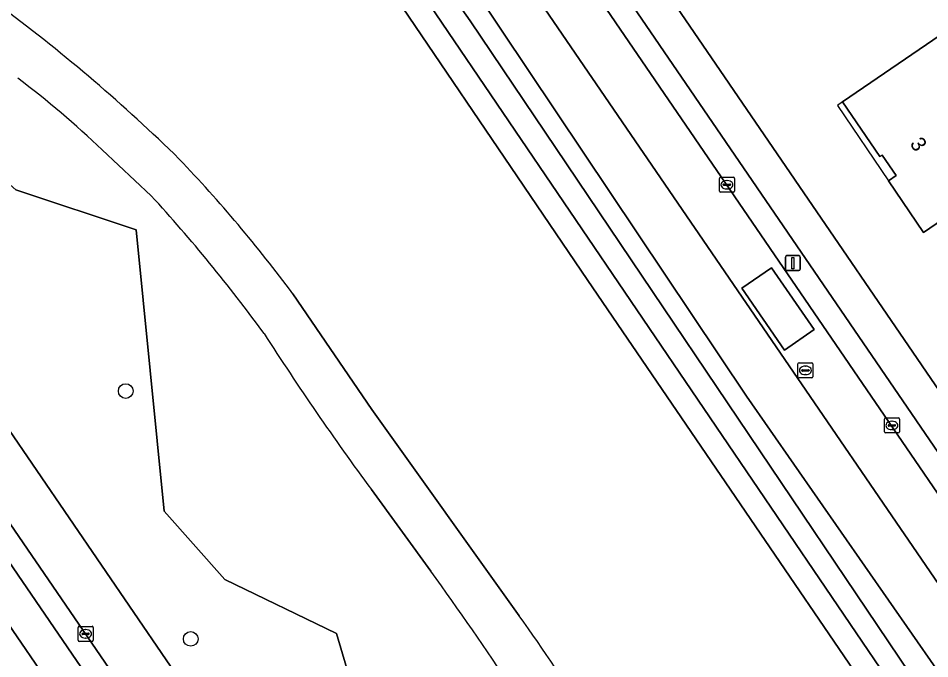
# Model space of a CAD drawing. Extents: x 155275 to 156265, y 382654 to 383635.
# Drawn here: x 155646.9 to 155707.5, y 383225.8 to 383268.4 of the extents above; entities that cross this region are included whole.
import ezdxf

# ---------------------------------------------------------------- set-up
doc = ezdxf.new("R2010")
doc.units = 0
for name, color, linetype in [('IMGEO_Boom', 7, 'Continuous'), ('IMGEO_Erf', 7, 'Continuous'), ('IMGEO_Fietspad_gesloten', 7, 'Continuous'), ('IMGEO_Gemengd_bos', 7, 'Continuous'), ('IMGEO_Groenvoorziening', 7, 'Continuous'), ('IMGEO_Haag', 7, 'Continuous'), ('IMGEO_Kolk', 7, 'Continuous'), ('IMGEO_Lichtmast', 7, 'Continuous'), ('IMGEO_Loofbos', 7, 'Continuous'), ('IMGEO_Oever', 7, 'Continuous'), ('IMGEO_Pand', 7, 'Continuous'), ('IMGEO_Pand_nummerreeks', 7, 'Continuous'), ('IMGEO_Pand_overbouw', 7, 'Continuous'), ('IMGEO_Rijbaan_lokaal_gesloten', 7, 'Continuous'), ('IMGEO_Rijbaan_lokaal_open', 7, 'Continuous'), ('IMGEO_Rioolput', 7, 'Continuous'), ('IMGEO_Voetpad_open', 7, 'Continuous'), ('IMGEO_Waterloop', 7, 'Continuous')]:
    doc.layers.add(name, color=color, linetype=linetype)

msp = doc.modelspace()

# ---------------------------------------------------------------- linework, layer by layer
at = {"layer": 'IMGEO_Boom'}
for centre in [(155654.008, 383243.637), (155658.327, 383227.152)]:
    msp.add_circle(centre, 0.489, dxfattribs=at)
at = {"layer": 'IMGEO_Erf'}
for points in [[(155685.56, 383327.69), (155661.788, 383311.41), (155661.818, 383311.37), (155722.08, 383223.219), (155746.422, 383187.612), (155746.888, 383186.944), (155747.971, 383187.224)], [(155641.945, 383174.729), (155651.229, 383182.342), (155649.626, 383184.602), (155649.758, 383184.692), (155647.793, 383187.593), (155649.873, 383189.002), (155652.548, 383190.814), (155652.458, 383190.947), (155653.046, 383191.345), (155649.869, 383196.034), (155649.737, 383195.945), (155649.406, 383196.433), (155657.792, 383202.114), (155662.684, 383194.892), (155659.46, 383192.694), (155659.082, 383193.248), (155657.359, 383192.071), (155659.44, 383189.029), (155668.128, 383196.041), (155626.917, 383256.363)]]:
    msp.add_lwpolyline(points, dxfattribs=at)
msp.add_lwpolyline([(155728.147, 383268.629), (155707.057, 383254.188), (155704.717, 383257.623), (155705.227, 383257.972), (155704.294, 383259.337), (155704.145, 383259.236), (155701.658, 383262.871), (155710.458, 383268.888), (155710.791, 383268.434), (155710.55, 383268.256), (155713.354, 383264.091), (155713.617, 383264.267), (155717.71, 383267.089), (155718.705, 383265.728), (155721.105, 383267.326), (155720.14, 383268.738), (155725.534, 383272.422)], close=True, dxfattribs=at)
at = {"layer": 'IMGEO_Fietspad_gesloten'}
for points in [[(155652.45, 383259.676), (155655.699, 383256.63)], [(155680.172, 383228.685), (155670.36, 383242.418), (155665.114, 383250.113)], [(155670.339, 383237.079), (155674.294, 383231.647)]]:
    msp.add_lwpolyline(points, dxfattribs=at)
for centre, radius, start, end in [((155578.477, 383178.43), 112.95, 45.55812, 53.3606), ((155607.857, 383212.844), 64.666, 46.40321, 52.93409), ((155588.907, 383193.545), 94.907, 36.58657, 43.66446), ((155578.317, 383185.637), 105.014, 36.06418, 42.53436), ((155836.246, 383358.739), 205.733, 212.74499, 216.25284), ((155514.469, 383115.222), 197.734, 30.54809, 36.07145), ((155565.087, 383146.707), 141.298, 28.66651, 35.46317)]:
    msp.add_arc(centre, radius, start, end, dxfattribs=at)
at = {"layer": 'IMGEO_Gemengd_bos'}
for points in [[(155638.354, 383264.775), (155639.197, 383263.636), (155646.696, 383257.021), (155654.699, 383254.352), (155656.556, 383235.653), (155660.593, 383231.109), (155668.02, 383227.503), (155671.061, 383217.227), (155677.612, 383213.971), (155684.929, 383206.792), (155680.581, 383201.856), (155690.881, 383188.232), (155700.213, 383173.291), (155708, 383167.974), (155712.849, 383162.916), (155715.835, 383169.166), (155716.917, 383171.91)], [(155655.699, 383256.63), (155652.45, 383259.676)], [(155674.294, 383231.647), (155670.339, 383237.079)]]:
    msp.add_lwpolyline(points, dxfattribs=at)
for centre, radius, start, end in [((155607.857, 383212.844), 64.666, 46.40321, 52.93409), ((155578.317, 383185.637), 105.014, 36.06418, 42.53436), ((155836.246, 383358.739), 205.733, 212.74499, 216.25284), ((155514.469, 383115.222), 197.734, 30.54809, 36.07145)]:
    msp.add_arc(centre, radius, start, end, dxfattribs=at)
at = {"layer": 'IMGEO_Groenvoorziening'}
for points in [[(155724.288, 383171.628), (155724.536, 383171.272), (155727.184, 383173.115), (155741.62, 383181.726), (155659.414, 383301.908), (155653.216, 383310.97)], [(155661.264, 383305.321), (155662.23, 383303.795), (155718.824, 383220.994), (155726.923, 383209.144), (155742.91, 383185.882), (155743.508, 383186.026), (155744.463, 383186.256), (155720.116, 383221.876), (155661.229, 383308.029)], [(155652.603, 383306.481), (155666.3, 383286.64), (155695.288, 383243.3), (155715.747, 383213.896), (155732.948, 383189.534)], [(155712.849, 383162.916), (155708, 383167.974), (155700.213, 383173.291), (155690.881, 383188.232), (155680.581, 383201.856), (155684.929, 383206.792), (155677.612, 383213.971), (155671.061, 383217.227), (155668.02, 383227.503), (155660.593, 383231.109), (155656.556, 383235.653), (155654.699, 383254.352), (155646.696, 383257.021), (155639.197, 383263.636), (155638.354, 383264.775)], [(155634.953, 383262.987), (155633.988, 383262.853), (155632.89, 383262.908), (155632.326, 383262.839), (155631.606, 383262.467), (155632.286, 383261.472), (155635.169, 383257.252), (155673.892, 383200.579), (155675.129, 383198.768), (155704.368, 383155.976), (155709.386, 383160.082)]]:
    msp.add_lwpolyline(points, dxfattribs=at)
msp.add_lwpolyline([(155631.52, 383256.462), (155630.285, 383255.634), (155668.768, 383199.296), (155670.058, 383200.101), (155632.271, 383255.325)], close=True, dxfattribs=at)
at = {"layer": 'IMGEO_Haag'}
msp.add_lwpolyline([(155661.264, 383305.321), (155662.23, 383303.795), (155718.824, 383220.994), (155726.923, 383209.144), (155742.91, 383185.882), (155743.508, 383186.026), (155744.463, 383186.256), (155720.116, 383221.876), (155661.229, 383308.029)], dxfattribs=at)
msp.add_lwpolyline([(155631.52, 383256.462), (155630.285, 383255.634), (155668.768, 383199.296), (155670.058, 383200.101), (155632.271, 383255.325)], close=True, dxfattribs=at)
at = {"layer": 'IMGEO_Kolk'}
for p, q in [((155693.482, 383256.936), (155693.482, 383257.788)), ((155693.557, 383257.862), (155694.409, 383257.862)), ((155693.97, 383257.642), (155693.995, 383257.642)), ((155694.483, 383257.788), (155694.483, 383256.936)), ((155693.741, 383257.356), (155693.741, 383257.368)), ((155694.179, 383257.319), (155693.781, 383257.319)), ((155693.784, 383257.405), (155694.182, 383257.405)), ((155693.993, 383257.082), (155693.968, 383257.082)), ((155694.225, 383257.368), (155694.225, 383257.356)), ((155694.409, 383256.862), (155693.557, 383256.862)), ((155704.449, 383240.924), (155704.449, 383241.776)), ((155704.524, 383241.85), (155705.376, 383241.85)), ((155705.45, 383241.776), (155705.45, 383240.924)), ((155704.708, 383241.344), (155704.708, 383241.356)), ((155705.146, 383241.307), (155704.748, 383241.307)), ((155704.751, 383241.393), (155705.149, 383241.393)), ((155704.937, 383241.63), (155704.962, 383241.63)), ((155705.192, 383241.356), (155705.192, 383241.344)), ((155705.376, 383240.85), (155704.524, 383240.85)), ((155704.96, 383241.07), (155704.935, 383241.07)), ((155650.837, 383227.061), (155650.837, 383227.913)), ((155650.912, 383227.987), (155651.764, 383227.987)), ((155651.838, 383227.913), (155651.838, 383227.061)), ((155651.096, 383227.481), (155651.096, 383227.493)), ((155651.534, 383227.444), (155651.136, 383227.444)), ((155651.139, 383227.53), (155651.537, 383227.53)), ((155651.348, 383227.207), (155651.323, 383227.207)), ((155651.325, 383227.767), (155651.35, 383227.767)), ((155651.58, 383227.493), (155651.58, 383227.481)), ((155651.764, 383226.987), (155650.912, 383226.987))]:
    msp.add_line(p, q, dxfattribs=at)
for points in [[(155693.482, 383256.936), (155693.482, 383257.788)], [(155693.557, 383257.862), (155694.409, 383257.862)], [(155694.483, 383257.788), (155694.483, 383256.936)], [(155694.409, 383256.862), (155693.557, 383256.862)], [(155704.449, 383240.924), (155704.449, 383241.776)], [(155704.524, 383241.85), (155705.376, 383241.85)], [(155705.45, 383241.776), (155705.45, 383240.924)], [(155705.376, 383240.85), (155704.524, 383240.85)], [(155650.837, 383227.061), (155650.837, 383227.913)], [(155650.912, 383227.987), (155651.764, 383227.987)], [(155651.838, 383227.913), (155651.838, 383227.061)], [(155651.764, 383226.987), (155650.912, 383226.987)]]:
    msp.add_lwpolyline(points, dxfattribs=at)
for centre, radius, start, end in [((155693.559, 383257.786), 0.0765, 91.55205, 178.44795), ((155693.559, 383257.786), 0.0765, 91.55205, 178.44795), ((155694.407, 383257.786), 0.0765, 1.55205, 88.44795), ((155694.407, 383257.786), 0.0765, 1.55205, 88.44795), ((155693.559, 383256.938), 0.0765, 181.55205, 268.44795), ((155693.559, 383256.938), 0.0765, 181.55205, 268.44795), ((155693.781, 383257.365), 0.0403, 85.87752, 175.75265), ((155693.778, 383257.355), 0.0366, 178.93798, 274.71019), ((155694.182, 383257.362), 0.043, 264.86636, 352.45326), ((155694.186, 383257.367), 0.0386, 1.73085, 96.63898), ((155694.407, 383256.938), 0.0765, 271.55205, 358.44795), ((155694.407, 383256.938), 0.0765, 271.55205, 358.44795), ((155704.526, 383241.774), 0.0765, 91.55205, 178.44795), ((155704.526, 383241.774), 0.0765, 91.55205, 178.44795), ((155705.374, 383241.774), 0.0765, 1.55205, 88.44795), ((155705.374, 383241.774), 0.0765, 1.55205, 88.44795), ((155704.748, 383241.353), 0.0403, 85.87752, 175.75265), ((155704.745, 383241.343), 0.0366, 178.93798, 274.71019), ((155705.149, 383241.35), 0.043, 264.86636, 352.45326), ((155705.153, 383241.355), 0.0386, 1.73085, 96.63898), ((155704.526, 383240.926), 0.0765, 181.55205, 268.44795), ((155704.526, 383240.926), 0.0765, 181.55205, 268.44795), ((155705.374, 383240.926), 0.0765, 271.55205, 358.44795), ((155705.374, 383240.926), 0.0765, 271.55205, 358.44795), ((155650.914, 383227.911), 0.0765, 91.55205, 178.44795), ((155650.914, 383227.911), 0.0765, 91.55205, 178.44795), ((155651.762, 383227.911), 0.0765, 1.55205, 88.44795), ((155651.762, 383227.911), 0.0765, 1.55205, 88.44795), ((155651.136, 383227.49), 0.0403, 85.87752, 175.75265), ((155651.133, 383227.48), 0.0366, 178.93798, 274.71019), ((155651.537, 383227.487), 0.043, 264.86636, 352.45326), ((155651.541, 383227.492), 0.0386, 1.73085, 96.63898), ((155650.914, 383227.063), 0.0765, 181.55205, 268.44795), ((155650.914, 383227.063), 0.0765, 181.55205, 268.44795), ((155651.762, 383227.063), 0.0765, 271.55205, 358.44795), ((155651.762, 383227.063), 0.0765, 271.55205, 358.44795)]:
    msp.add_arc(centre, radius, start, end, dxfattribs=at)
for centre, major_axis, ratio, start_param, end_param in [((155693.969, 383257.362), (-0.387, 0.002), 0.722429, 4.712389, 7.853982), ((155693.994, 383257.362), (-0.39, 0.002), 0.717154, 1.570796, 4.712389), ((155704.936, 383241.35), (-0.387, 0.002), 0.722429, 4.712389, 7.853982), ((155704.961, 383241.35), (-0.39, 0.002), 0.717154, 1.570796, 4.712389), ((155651.324, 383227.487), (-0.387, 0.002), 0.722429, 4.712389, 7.853982), ((155651.349, 383227.487), (-0.39, 0.002), 0.717154, 1.570796, 4.712389)]:
    msp.add_ellipse(centre, major_axis=major_axis, ratio=ratio, start_param=start_param, end_param=end_param, dxfattribs=at)
at = {"layer": 'IMGEO_Lichtmast'}
for p, q in [((155697.868, 383251.75), (155697.868, 383252.55)), ((155697.868, 383252.55), (155697.868, 383251.75)), ((155697.968, 383252.65), (155698.758, 383252.65)), ((155698.758, 383252.65), (155697.968, 383252.65)), ((155698.858, 383252.55), (155698.858, 383251.75)), ((155698.858, 383251.75), (155698.858, 383252.55)), ((155698.758, 383251.65), (155697.968, 383251.65)), ((155697.968, 383251.65), (155698.758, 383251.65))]:
    msp.add_line(p, q, dxfattribs=at)
msp.add_lwpolyline([(155698.288, 383252.525), (155698.438, 383252.525), (155698.438, 383251.775), (155698.288, 383251.775), (155698.288, 383252.525)], dxfattribs=at)
for centre, start, end in [((155697.968, 383252.55), 90, 180), ((155697.968, 383252.55), 90, 180), ((155698.758, 383252.55), 0, 90), ((155698.758, 383252.55), 360, 90), ((155697.968, 383251.75), 180, 270), ((155697.968, 383251.75), 180, 270), ((155698.758, 383251.75), 270, 0), ((155698.758, 383251.75), 270, 0)]:
    msp.add_arc(centre, 0.1, start, end, dxfattribs=at)
at = {"layer": 'IMGEO_Loofbos'}
for points in [[(155710.048, 383179.361), (155711.113, 383178.69), (155722.162, 383175.473), (155727.137, 383176.194), (155728.723, 383186.646), (155722.016, 383196.56), (155713.872, 383208.237), (155684.729, 383250.992), (155668.129, 383275.492), (155648.012, 383304.606)], [(155665.114, 383250.113), (155670.36, 383242.418), (155680.172, 383228.685)]]:
    msp.add_lwpolyline(points, dxfattribs=at)
for centre, radius, start, end in [((155578.477, 383178.43), 112.95, 45.55812, 53.3606), ((155588.907, 383193.545), 94.907, 36.58657, 43.66446), ((155565.087, 383146.707), 141.298, 28.66651, 35.46317)]:
    msp.add_arc(centre, radius, start, end, dxfattribs=at)
at = {"layer": 'IMGEO_Oever'}
msp.add_lwpolyline([(155731.242, 383188.308), (155731.02, 383187.751), (155730.364, 383187.664), (155714.72, 383209.654), (155670.177, 383275.322), (155648.619, 383307.02), (155649.298, 383307.441), (155676.91, 383268.261), (155714.708, 383212.148)], close=True, dxfattribs=at)
for points in [[(155732.948, 383189.534), (155715.747, 383213.896), (155695.288, 383243.3), (155666.3, 383286.64), (155652.603, 383306.481)], [(155648.012, 383304.606), (155668.129, 383275.492), (155684.729, 383250.992), (155713.872, 383208.237), (155722.016, 383196.56), (155728.723, 383186.646)]]:
    msp.add_lwpolyline(points, dxfattribs=at)
at = {"layer": 'IMGEO_Pand'}
msp.add_lwpolyline([(155704.717, 383257.623), (155707.057, 383254.188), (155728.147, 383268.629), (155725.534, 383272.422), (155720.14, 383268.738), (155721.105, 383267.326), (155718.705, 383265.728), (155717.71, 383267.089), (155713.617, 383264.267), (155713.354, 383264.091), (155710.55, 383268.256), (155710.791, 383268.434), (155710.458, 383268.888), (155701.658, 383262.871), (155704.145, 383259.236), (155704.294, 383259.337), (155705.227, 383257.972)], close=True, dxfattribs=at)
at = {"layer": 'IMGEO_Pand_overbouw'}
msp.add_lwpolyline([(155701.658, 383262.871), (155701.335, 383262.627), (155704.717, 383257.623), (155705.227, 383257.972), (155704.294, 383259.337), (155704.145, 383259.236)], close=True, dxfattribs=at)
at = {"layer": 'IMGEO_Rijbaan_lokaal_gesloten'}
for points in [[(155662.23, 383303.795), (155659.414, 383301.908), (155741.62, 383181.726), (155742.144, 383180.959)], [(155743.419, 383185.124), (155742.91, 383185.882), (155726.923, 383209.144), (155718.824, 383220.994), (155662.23, 383303.795)], [(155675.129, 383198.768), (155673.892, 383200.579), (155635.169, 383257.252), (155632.271, 383255.325), (155670.058, 383200.101), (155671.161, 383198.489), (155674.425, 383193.719), (155676.345, 383190.914), (155698.997, 383157.808)]]:
    msp.add_lwpolyline(points, dxfattribs=at)
msp.add_lwpolyline([(155697.801, 383246.357), (155694.964, 383250.49), (155696.947, 383251.843), (155699.774, 383247.725)], close=True, dxfattribs=at)
at = {"layer": 'IMGEO_Rijbaan_lokaal_open'}
msp.add_lwpolyline([(155697.801, 383246.357), (155699.774, 383247.725), (155696.947, 383251.843), (155694.964, 383250.49)], close=True, dxfattribs=at)
at = {"layer": 'IMGEO_Rioolput'}
for p, q in [((155698.7, 383244.587), (155698.7, 383245.439)), ((155698.775, 383245.513), (155699.627, 383245.513)), ((155699.701, 383245.439), (155699.701, 383244.587)), ((155698.959, 383245.007), (155698.959, 383245.019)), ((155699.397, 383244.97), (155698.999, 383244.97)), ((155699.002, 383245.056), (155699.4, 383245.056)), ((155699.188, 383245.293), (155699.213, 383245.293)), ((155699.443, 383245.019), (155699.443, 383245.007)), ((155699.627, 383244.513), (155698.775, 383244.513)), ((155699.211, 383244.733), (155699.186, 383244.733))]:
    msp.add_line(p, q, dxfattribs=at)
for points in [[(155698.7, 383244.587), (155698.7, 383245.439)], [(155698.775, 383245.513), (155699.627, 383245.513)], [(155699.701, 383245.439), (155699.701, 383244.587)], [(155699.627, 383244.513), (155698.775, 383244.513)]]:
    msp.add_lwpolyline(points, dxfattribs=at)
for centre, radius, start, end in [((155698.777, 383245.437), 0.0765, 91.55205, 178.44795), ((155698.777, 383245.437), 0.0765, 91.55205, 178.44795), ((155699.625, 383245.437), 0.0765, 1.55205, 88.44795), ((155699.625, 383245.437), 0.0765, 1.55205, 88.44795), ((155698.999, 383245.016), 0.0403, 85.87752, 175.75265), ((155698.996, 383245.006), 0.0366, 178.93798, 274.71019), ((155699.4, 383245.013), 0.043, 264.86636, 352.45326), ((155699.404, 383245.018), 0.0386, 1.73085, 96.63898), ((155698.777, 383244.589), 0.0765, 181.55205, 268.44795), ((155698.777, 383244.589), 0.0765, 181.55205, 268.44795), ((155699.625, 383244.589), 0.0765, 271.55205, 358.44795), ((155699.625, 383244.589), 0.0765, 271.55205, 358.44795)]:
    msp.add_arc(centre, radius, start, end, dxfattribs=at)
for centre, major_axis, ratio, start_param, end_param in [((155699.187, 383245.013), (-0.387, 0.002), 0.722429, 4.712389, 7.853982), ((155699.212, 383245.013), (-0.39, 0.002), 0.717154, 1.570796, 4.712389)]:
    msp.add_ellipse(centre, major_axis=major_axis, ratio=ratio, start_param=start_param, end_param=end_param, dxfattribs=at)
at = {"layer": 'IMGEO_Voetpad_open'}
for points in [[(155660.2, 383309.537), (155661.229, 383308.029), (155720.116, 383221.876), (155744.463, 383186.256), (155746.888, 383186.944), (155746.422, 383187.612), (155722.08, 383223.219), (155661.818, 383311.37)], [(155624.836, 383259.458), (155625.364, 383258.662), (155626.917, 383256.363), (155668.128, 383196.041), (155669.974, 383197.531), (155671.161, 383198.489), (155670.058, 383200.101), (155668.768, 383199.296), (155630.285, 383255.634)]]:
    msp.add_lwpolyline(points, dxfattribs=at)
at = {"layer": 'IMGEO_Waterloop'}
msp.add_lwpolyline([(155648.619, 383307.02), (155670.177, 383275.322), (155714.72, 383209.654), (155730.364, 383187.664), (155731.02, 383187.751), (155731.242, 383188.308), (155714.708, 383212.148), (155676.91, 383268.261), (155649.298, 383307.441)], close=True, dxfattribs=at)

# ---------------------------------------------------------------- texts
at = {"layer": 'IMGEO_Pand_nummerreeks'}
msp.add_text('3', height=1, rotation=304.16244, dxfattribs=at).set_placement((155706.104, 383260.095))

doc.saveas('drawing.dxf')
